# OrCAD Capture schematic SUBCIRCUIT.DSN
size A
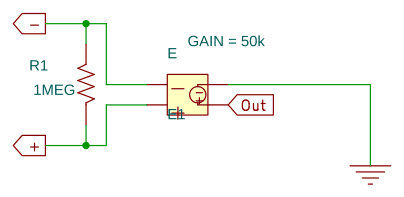
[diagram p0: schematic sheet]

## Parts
E1  E
R1  1MEG  [AX/RC05]

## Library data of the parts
E1 = E: GAIN: 50k
R1 = R

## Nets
0: E1.4
+: E1.1 R1.1
-: E1.2 R1.2
Out: E1.3
